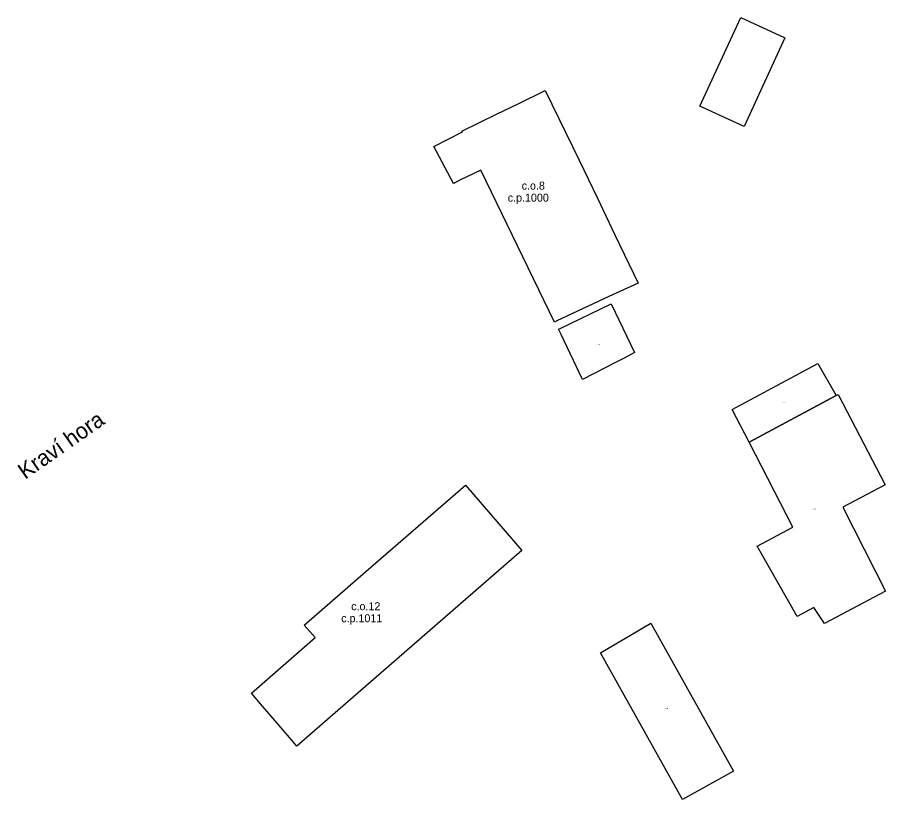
# Model space of a CAD drawing. Extents: x -600391 to -599491, y -1160176 to -1159402.
# Drawn here: x -599716.9 to -599608.4, y -1159767.1 to -1159669.4 of the extents above; entities that cross this region are included whole.
import ezdxf

# ---------------------------------------------------------------- set-up
doc = ezdxf.new("R2010")
doc.units = 0
for name, color, linetype in [('Level 10', 7, 'Continuous'), ('Level 11', 7, 'Continuous'), ('Level 12', 7, 'Continuous'), ('Level 24', 7, 'Continuous'), ('Level 61', 7, 'Continuous'), ('Level 62', 7, 'Continuous')]:
    doc.layers.add(name, color=color, linetype=linetype)

msp = doc.modelspace()

# ---------------------------------------------------------------- linework, layer by layer
at = {"layer": 'Level 61'}
for points in [[(-599631.61, -1159680.5), (-599626.5, -1159669.42)], [(-599626.5, -1159669.42), (-599620.97, -1159671.97)], [(-599620.97, -1159671.97), (-599626.08, -1159683.05)], [(-599654.38, -1159680.24), (-599650.92, -1159678.57)], [(-599650.92, -1159678.57), (-599646.7, -1159687.23)], [(-599656.93, -1159681.47), (-599654.38, -1159680.24)], [(-599626.08, -1159683.05), (-599631.61, -1159680.5)], [(-599661.34, -1159683.61), (-599656.93, -1159681.47)], [(-599664.84, -1159685.55), (-599661.28, -1159683.7)], [(-599661.28, -1159683.7), (-599661.34, -1159683.61)], [(-599662.38, -1159690.18), (-599664.84, -1159685.55)], [(-599646.7, -1159687.23), (-599644.41, -1159692.01)], [(-599658.96, -1159688.48), (-599661.5, -1159689.71)], [(-599649.76, -1159707.46), (-599658.96, -1159688.48)], [(-599662.34, -1159690.16), (-599662.38, -1159690.18)], [(-599662.23, -1159690.1), (-599662.34, -1159690.16)], [(-599661.5, -1159689.71), (-599662.23, -1159690.1)], [(-599644.41, -1159692.01), (-599642.22, -1159696.57)], [(-599642.22, -1159696.57), (-599639.32, -1159702.61)], [(-599639.32, -1159702.61), (-599642.98, -1159704.28)], [(-599642.98, -1159704.28), (-599649.48, -1159707.33)], [(-599649.04, -1159708.26), (-599642.68, -1159705.2)], [(-599642.68, -1159705.2), (-599639.76, -1159711.28)], [(-599649.48, -1159707.33), (-599649.76, -1159707.46)], [(-599649.26, -1159708.37), (-599649.04, -1159708.26)], [(-599648.95, -1159709.03), (-599649.26, -1159708.37)], [(-599646.26, -1159714.65), (-599648.95, -1159709.03)], [(-599641.08, -1159711.96), (-599642.15, -1159712.51)], [(-599639.76, -1159711.28), (-599641.08, -1159711.96)], [(-599642.15, -1159712.51), (-599646.26, -1159714.65)], [(-599627.57, -1159718.38), (-599616.85, -1159712.62)], [(-599616.85, -1159712.62), (-599614.56, -1159716.63)], [(-599614.56, -1159716.63), (-599614.34, -1159716.51)], [(-599614.34, -1159716.51), (-599608.43, -1159727.8)], [(-599614.56, -1159716.63), (-599625.45, -1159722.48)], [(-599625.45, -1159722.48), (-599614.56, -1159716.63)], [(-599625.45, -1159722.48), (-599627.57, -1159718.38)], [(-599619.99, -1159733.07), (-599625.45, -1159722.48)], [(-599673.33, -1159738.63), (-599660.9, -1159727.84)], [(-599660.9, -1159727.84), (-599653.83, -1159735.98)], [(-599608.43, -1159727.8), (-599613.75, -1159730.59)], [(-599613.75, -1159730.59), (-599608.39, -1159741.06)], [(-599624.43, -1159735.47), (-599619.99, -1159733.07)], [(-599653.83, -1159735.98), (-599681.95, -1159760.43)], [(-599619.45, -1159744.23), (-599624.43, -1159735.47)], [(-599681.03, -1159745.32), (-599673.33, -1159738.63)], [(-599608.39, -1159741.06), (-599616.04, -1159745.09)], [(-599617.37, -1159743.13), (-599619.45, -1159744.23)], [(-599616.04, -1159745.09), (-599617.37, -1159743.13)], [(-599679.68, -1159746.86), (-599681.03, -1159745.32)], [(-599644.03, -1159748.79), (-599637.75, -1159745.06)], [(-599637.75, -1159745.06), (-599627.4, -1159763.53)], [(-599687.63, -1159753.81), (-599679.68, -1159746.86)], [(-599633.76, -1159767.1), (-599644.03, -1159748.79)], [(-599686.49, -1159755.15), (-599687.63, -1159753.81)], [(-599682.62, -1159759.65), (-599686.49, -1159755.15)], [(-599681.95, -1159760.43), (-599682.62, -1159759.65)], [(-599627.4, -1159763.53), (-599633.76, -1159767.1)]]:
    msp.add_lwpolyline(points, dxfattribs=at)
at = {"layer": 'Level 62'}
for points in [[(-599626.5, -1159669.42), (-599620.97, -1159671.97), (-599626.08, -1159683.05), (-599631.61, -1159680.5), (-599626.5, -1159669.42)], [(-599644.41, -1159692.01), (-599642.22, -1159696.57), (-599639.32, -1159702.61), (-599642.98, -1159704.28), (-599649.48, -1159707.33), (-599649.76, -1159707.46), (-599658.96, -1159688.48), (-599661.5, -1159689.71), (-599662.23, -1159690.1), (-599662.34, -1159690.16), (-599662.38, -1159690.18), (-599664.84, -1159685.55), (-599661.28, -1159683.7), (-599661.34, -1159683.61), (-599656.93, -1159681.47), (-599654.38, -1159680.24), (-599650.92, -1159678.57), (-599646.7, -1159687.23), (-599644.41, -1159692.01)], [(-599642.15, -1159712.51), (-599646.26, -1159714.65), (-599648.95, -1159709.03), (-599649.26, -1159708.37), (-599649.04, -1159708.26), (-599642.68, -1159705.2), (-599639.76, -1159711.28), (-599641.08, -1159711.96), (-599642.15, -1159712.51)], [(-599625.45, -1159722.48), (-599627.57, -1159718.38), (-599616.85, -1159712.62), (-599614.56, -1159716.63), (-599625.45, -1159722.48)], [(-599625.45, -1159722.48), (-599614.56, -1159716.63), (-599614.34, -1159716.51), (-599608.43, -1159727.8), (-599613.75, -1159730.59), (-599608.39, -1159741.06), (-599616.04, -1159745.09), (-599617.37, -1159743.13), (-599619.45, -1159744.23), (-599624.43, -1159735.47), (-599619.99, -1159733.07), (-599625.45, -1159722.48)], [(-599660.9, -1159727.84), (-599653.83, -1159735.98), (-599681.95, -1159760.43), (-599682.62, -1159759.65), (-599686.49, -1159755.15), (-599687.63, -1159753.81), (-599679.68, -1159746.86), (-599681.03, -1159745.32), (-599673.33, -1159738.63), (-599660.9, -1159727.84)], [(-599644.03, -1159748.79), (-599637.75, -1159745.06), (-599627.4, -1159763.53), (-599633.76, -1159767.1), (-599644.03, -1159748.79)]]:
    msp.add_lwpolyline(points, dxfattribs=at)

# ---------------------------------------------------------------- texts
at = {"layer": 'Level 10'}
for s, p in [('c.o.8', (-599653.87, -1159690.93)), ('c.o.12', (-599675.17, -1159743.45))]:
    msp.add_text(s, height=1, dxfattribs=at).set_placement(p)
at = {"layer": 'Level 11'}
msp.add_text('Kraví hora', height=2, rotation=35.0354, dxfattribs=at).set_placement((-599715.92, -1159727.18))
at = {"layer": 'Level 12'}
for s, p in [('c.p.1000', (-599655.61, -1159692.43)), ('c.p.1011', (-599676.42, -1159744.95))]:
    msp.add_text(s, height=1, dxfattribs=at).set_placement(p)
at = {"layer": 'Level 24'}
for s, p in [('c.z.608', (-599644.53, -1159710.35)), ('c.z.751', (-599621.33, -1159717.55)), ('c.z.653', (-599617.57, -1159730.84)), ('c.z.893', (-599636.03, -1159755.77))]:
    msp.add_text(s, height=0.1, dxfattribs=at).set_placement(p)

doc.saveas('drawing.dxf')
